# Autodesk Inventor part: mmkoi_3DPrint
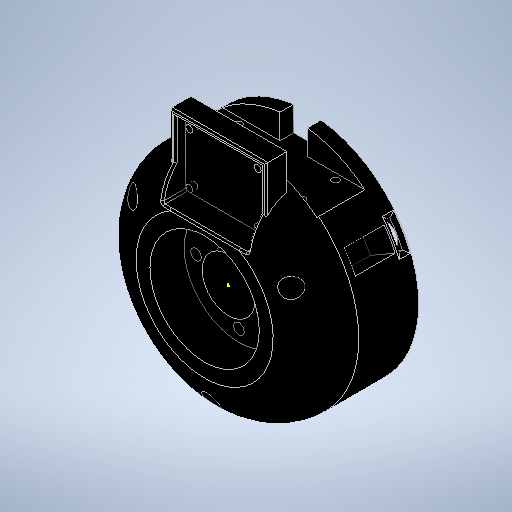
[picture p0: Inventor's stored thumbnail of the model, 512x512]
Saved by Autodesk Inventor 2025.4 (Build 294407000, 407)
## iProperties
Created: 2026-05
Part Number: mmkoi_3DPrint
Material: Generic
Document SubType Name: Modeling
Designer: PC
Density: 1 g/cm^3
Appearance: Default
Author: PC
Part Number: SOPORTE-SERVOMOTOR
Material: LCP Plastic
Density: 1.626 g/cm^3
Appearance: Anodized - Black
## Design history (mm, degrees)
sketch "Sketch1"
  geometry: C1 r 31.9 at (0, 0); C2 r 15.5 at (0, 0); C3 r 50 at (0, 0); 1 further point
  constraints: 3 centre point, 3 coincident
  dimensions: "d0" = 63.8 diameter of C1; "d1" = 31 diameter of C2; "d2" = 100 diameter of C3
extrude "Extrusion1" new body sketch "Sketch1" distance "d3" = 6; taper "d4" = 0 deg
extrude "Extrusion2" join sketch "Sketch1" distance "d5" = 5; taper "d6" = 0 deg
extrude "Extrusion3" join sketch "Sketch1" distance "d7" = 20; taper "d8" = 0 deg
sketch "Sketch2" dims "d124" = 50
  geometry: L1 (0, 0)-(0, 57.814); L2 (0, 57.814)-(0, -61.092); L3 (0, 0)-(70.653, 0); L4 (-12.139, 32.9)-(19.855, 32.9); L5 (0, 29.9)-(2.345, 29.9); C1 r 31.5 at (0, 0); C2 r 50 at (0, 0) reference; C3 r 31.5 at (0, 0); C4 r 3.1 at (0, 25); C5 r 3.1 at (-25, 0); C6 r 3.1 at (0, -25); C7 r 3.1 at (25, 0); 3 further points
  constraints: 10 end point, 6 centre point, 3 coincident, 3 horizontal, 3 point on line, 1 concentric, 1 midpoint, 1 vertical, 1 vertical alignment, 11 other
  dimensions: "d125" = 6.2 diameter of C4; "d128" = 360 deg dimension on point (0, 0) C4.centre (derived)
extrude "Extrusion4" cut sketch "Sketch2" extent not by distance; stored distance "d15" = 0; taper "d16" = 0 deg
sketch "Sketch3"
  geometry: 1 further point
workplane "Work Plane1"
sketch "Sketch4"
  geometry: C1 r 45 at (0, 0); C2 r 65 at (0, 0); 1 further point
  constraints: 2 centre point, 2 coincident
  dimensions: "d18" = 90 diameter of C1; "d19" = 130 diameter of C2
extrude "Extrusion5" join sketch "Sketch4" distance "d20" = 10; taper "d21" = 0 deg
extrude "Extrusion6" join sketch "Sketch4" distance "d22" = 20; taper "d23" = 0 deg
workplane "Work Plane2"
sketch "Sketch7"
  geometry: L1 (0, 0)-(-74.528, -74.528); L2 (0, 0)-(105.399, 0); L3 (0, 0)-(58.543, 58.543); C1 r 45 at (0, 0) reference; C2 r 45 at (0, 0); C3 r 65 at (0, 0)
  constraints: 6 end point, 2 centre point, 2 coincident, 1 equal length, 1 horizontal
  dimensions: "d33" = 135 deg angle of L1 L2
extrude "Extrusion8" join sketch "Sketch7" distance "d34" = 15; taper "d35" = 0 deg
workplane "Work Plane3"
workplane "Work Plane4"
workplane "Work Plane5"
sketch "Sketch18"
  geometry: 1 further point
workaxis "Work Axis1"
extrude "Extrusion22" join sketch "Sketch4" distance "d130" = 25; taper "d131" = 0 deg
fillet "Fillet1" dims "d132" = 25
workplane "Work Plane6"
sketch "Sketch21"
  geometry: 1 further point
sketch "Sketch22"
  geometry: L1 (-70, -4)-(70, -4); L2 (70, -4)-(70, -32); L3 (70, -32)-(-70, -32); L4 (-70, -32)-(-70, -4); L5 (-65, -40)-(65, -40) reference; L6 (0, -40)-(0, -64.088); 2 further points
  constraints: 10 end point, 2 midpoint, 2 parallel, 1 horizontal, 1 perpendicular, 1 vertical
  dimensions: "d139" = 140 distance of L2.end L3.end; "d140" = 28 distance of L1.end L2.end; "d141" = 70 distance from line of point (70, -18) L6; "d146" = 8 distance between parallel lines of L5 L3
extrude "Extrusion23" cut sketch "Sketch22" distance "d142" = 15; taper "d143" = 0 deg
sketch "Sketch24"
  geometry: C1 r 7.5 at (0, -55); C2 r 45 at (0, 0) reference; C3 r 7.5 at (47.631, 27.5); C4 r 7.5 at (-47.631, 27.5); 1 further point
  constraints: 3 centre point, 7 other
  dimensions: "d147" = 15 diameter of C1; "d148" = 55 distance of C2.centre C1.centre; "d151" = 360 deg dimension on point (0, 0) C1.centre (derived)
extrude "Extrusion25" cut sketch "Sketch24" distance "d153" = 5; taper "d154" = 0 deg
sketch "Sketch25"
  geometry: 1 further point
workplane "Work Plane7"
sketch "Sketch26"
  geometry: L1 (25, 35.518)-(-25, 35.518); L2 (-25, 35.518)-(-25, 70.518); L3 (-25, 70.518)-(25, 70.518); L4 (25, 70.518)-(25, 35.518); 1 further point
  constraints: 8 end point, 2 parallel, 1 horizontal, 1 perpendicular
  dimensions: "d156" = 50 distance of L2.end L3.end; "d157" = 35 distance of L1.end L2.end; "d158" = 25 distance from line of L2 point (0, 0)
extrude "Extrusion26" cut sketch "Sketch26" distance "d159" = 17; taper "d160" = 0 deg
workplane "Work Plane8"
sketch "Sketch29"
  geometry: L1 (41.533, -32)-(-41.533, -32) reference; L2 (-6.4, -32)-(6.4, -32); L3 (6.4, -32)-(6.4, -8.8); L4 (6.4, -8.8)-(-6.4, -8.8); L5 (-6.4, -8.8)-(-6.4, -32); 2 further points
  constraints: 8 end point, 2 parallel, 1 horizontal, 1 perpendicular, 1 point on line
  dimensions: "d173" = 12.8 distance of L4.end L3.end; "d174" = 23.2 distance of L3.end L2.end; "d175" = 6.4 distance from line of point (0, 0) L3 (= d176); "d176" = 6.4 distance from line of point (0, 0) L5 (derived)
extrude "Extrusion29" cut sketch "Sketch29" distance "d177" = 17; taper "d178" = 0 deg
sketch "Sketch30"
  geometry: C1 r 5 at (0, -53.216); 1 further point
  constraints: 1 centre point
  dimensions: "d179" = 10 diameter of C1
extrude "Extrusion30" cut sketch "Sketch30" distance "d180" = 40; taper "d181" = 0 deg
extrude "Extrusion31" cut sketch "Sketch30" distance "d182" = 10; taper "d183" = 0 deg
pattern_circular "Circular Pattern2" dims "d185" = 360 deg
pattern_circular "Circular Pattern3" dims angle "d188" = 360 deg
sketch "Sketch31"
  geometry: C1 r 5 at (0, 0); C2 r 5.005 at (-92.394, 0); 1 further point
  constraints: 2 centre point
extrude "Extrusion33" cut sketch "Sketch31" distance "d195" = 15; taper "d196" = 0 deg
workplane "Work Plane9"
sketch "Sketch32"
  geometry: L1 (7.5, -35)-(-7.5, -35) reference; L2 (7.5, -40)-(7.5, -35) reference; L3 (-7.5, -35)-(7.5, -35); L4 (7.5, -35)-(7.5, -37.5); L5 (7.5, -37.5)-(-7.5, -37.5); L6 (-7.5, -37.5)-(-7.5, -35); 1 further point
  constraints: 8 end point, 2 parallel, 1 horizontal, 1 midpoint, 1 perpendicular
extrude "Extrusion34" cut sketch "Sketch32" distance "d198" = 10; taper "d199" = 0 deg
fillet "Fillet5" dims "d200" = 2
pattern_circular "Circular Pattern5" dims "d202" = 360 deg, "d204" = 0
sketch "Sketch34"
  geometry: L1 (25, 35.518)-(-25, 35.518) reference; L2 (-25, 35.518)-(25, 35.518); L3 (25, 35.518)-(25, 75.518); L4 (25, 75.518)-(-25, 75.518); L5 (-25, 75.518)-(-25, 35.518); 2 further points
  constraints: 8 end point, 2 parallel, 1 horizontal, 1 perpendicular
  dimensions: "d205" = 50 distance of L4.end L3.end; "d206" = 40 distance of L3.end L2.end
extrude "Extrusion35" join sketch "Sketch34" distance "d207" = 3; taper "d208" = 0 deg
extrude "Extrusion36" join sketch "Sketch34" distance "d209" = 3; taper "d210" = 0 deg
sketch "Sketch35"
  geometry: L1 (25, 35.518)-(-25, 35.518) reference; L2 (25, 57.228)-(25, 35.518) reference; L3 (25, 75.518)-(-25, 75.518) reference; L4 (-25, 35.518)-(-25, 57.228) reference; C1 r 2 at (20, 40.518); C2 r 2 at (20, 70.518); C3 r 2 at (-20, 40.518); C4 r 2 at (-20, 70.518); 1 further point
  constraints: 4 centre point
  dimensions: "d211" = 4 diameter of C1; "d212" = 5 distance from line of L1 C1.centre; "d213" = 5 distance from line of L2 C1.centre; "d214" = 4 diameter of C2; "d215" = 5 distance from line of L3 C2.centre; "d216" = 4 diameter of C3; "d217" = 5 distance from line of L1 C3.centre; "d218" = 5 distance from line of L4 C3.centre
extrude "Extrusion37" join sketch "Sketch35" distance "d219" = 3; taper "d220" = 0 deg
sketch "Sketch36"
  geometry: L1 (50, 6)-(0, 6) reference; L2 (0, -13.763)-(0, 0) reference; L3 (50, 6)-(0, 6); L4 (0, 6)-(0, -6); L5 (0, -6)-(50, -6); L6 (50, -6)-(50, 6); 3 further points
  constraints: 8 end point, 2 parallel, 1 horizontal, 1 perpendicular, 1 point on line
  dimensions: "d221" = 12 distance of L4.end L3.end
extrude "Extrusion38" join sketch "Sketch36" distance "d222" = 3; taper "d223" = 0 deg
sketch "Sketch37"
  geometry: L1 (0, 3)-(12, 3) reference; L2 (12, 3)-(0, 3); L3 (0, 3)-(0, -24.99); L4 (0, -24.99)-(12, -24.99); L5 (12, -24.99)-(12, 3); 2 further points
  constraints: 8 end point, 2 parallel, 1 horizontal, 1 perpendicular
extrude "Extrusion39" join sketch "Sketch37" distance "d224" = 3; taper "d225" = 0 deg
sketch "Sketch38"
  geometry: 1 further point
sketch "Sketch39"
  geometry: L1 (-6, 3)-(6, 3) reference; L2 (6, 3)-(6, -24.348) reference; L3 (-6, 3)-(6, 3); L4 (6, 3)-(6, -24.348); L5 (6, -24.348)-(-6, -24.348); L6 (-6, -24.348)-(-6, 3); 1 further point
  constraints: 8 end point, 2 parallel, 1 horizontal, 1 perpendicular
extrude "Extrusion40" join sketch "Sketch39" distance "d226" = 3; taper "d227" = 0 deg
fillet "Fillet6" dims "d228" = 1
sketch "Sketch40"
  geometry: 1 further point
sketch "Sketch41"
  geometry: L1 (30.967, 6)-(-31.533, 6); L2 (-31.533, 6)-(-31.533, 31.4); L3 (-31.533, 31.4)-(30.967, 31.4); L4 (30.967, 31.4)-(30.967, 6); L5 (-41.502, 4)-(41.502, 4) reference; L6 (-41.533, 5)-(-41.533, 32) reference; C1 r 2 at (27.967, 9); C2 r 2 at (-28.533, 9); C3 r 2 at (-28.533, 28.4); C4 r 2 at (27.967, 28.4); 2 further points
  constraints: 8 end point, 4 centre point, 2 parallel, 1 horizontal, 1 midpoint, 1 perpendicular
  dimensions: "d229" = 62.5 distance of L2.end L3.end; "d230" = 25.4 distance of L1.end L2.end; "d231" = 2 distance between parallel lines of L5 L1; "d232" = 10 distance from line of point (-41.533, 18.5) L2; "d233" = 4 diameter of C1; "d234" = 4 diameter of C2; "d235" = 4 diameter of C3; "d236" = 4 diameter of C4; "d237" = 3 distance from line of L3 C4.centre; "d238" = 3 distance from line of L4 C4.centre; "d239" = 3 distance from line of L3 C3.centre; "d240" = 3 distance from line of L2 C3.centre; "d241" = 3 distance from line of L2 C2.centre; "d242" = 3 distance from line of L1 C2.centre; "d243" = 3 distance from line of L1 C1.centre; "d244" = 3 distance from line of L4 C1.centre
extrude "Extrusion41" cut sketch "Sketch41" distance "d245" = 8; taper "d246" = 0 deg
sketch "Sketch42"
  geometry: 1 further point
sketch "Sketch43"
  geometry: L1 (-41.502, 50)-(41.502, 50) reference; L2 (-41.502, 50)-(41.502, 50); L3 (41.502, 50)-(0, 50); L4 (0, 50)-(0, 64.98); L5 (0, 50)-(8, 50); L6 (8, 50)-(8, 65); L7 (8, 65)-(0, 65); L8 (0, 65)-(0, 50); L9 (0, 65)-(-8, 65); L10 (-8, 65)-(-8, 50); L11 (-8, 50)-(0, 50); L12 (0, 50)-(0, 65); L13 (-8, 50)-(8, 50); L14 (8, 50)-(8, 65); L15 (8, 65)-(-8, 65); L16 (-8, 65)-(-8, 50); A1 r 64.98 centre (0, 0) between (41.502, 50) and (-41.502, 50) reference; 5 further points
  constraints: 30 end point, 7 equal length, 3 horizontal, 3 perpendicular, 1 midpoint, 1 point on circle, 1 point on line, 1 vertical
  dimensions: "d247" = 8 distance of L7.end L6.end; "d248" = 15 distance of L6.end L5.end; "d249" = 8 distance of L11.end L10.end
extrude "Extrusion42" cut sketch "Sketch43" distance "d250" = 8; taper "d251" = 0 deg
body "Solid1"
node "Sketch Circular Pattern3" dims "d128" = 360 deg (derived)
node "Sketch Circular Pattern4" dims "d151" = 360 deg (derived)
other parameters: "d24" = 65, "d133" = 65, "d155" = 0, "d172" = -65, "d197" = 17
